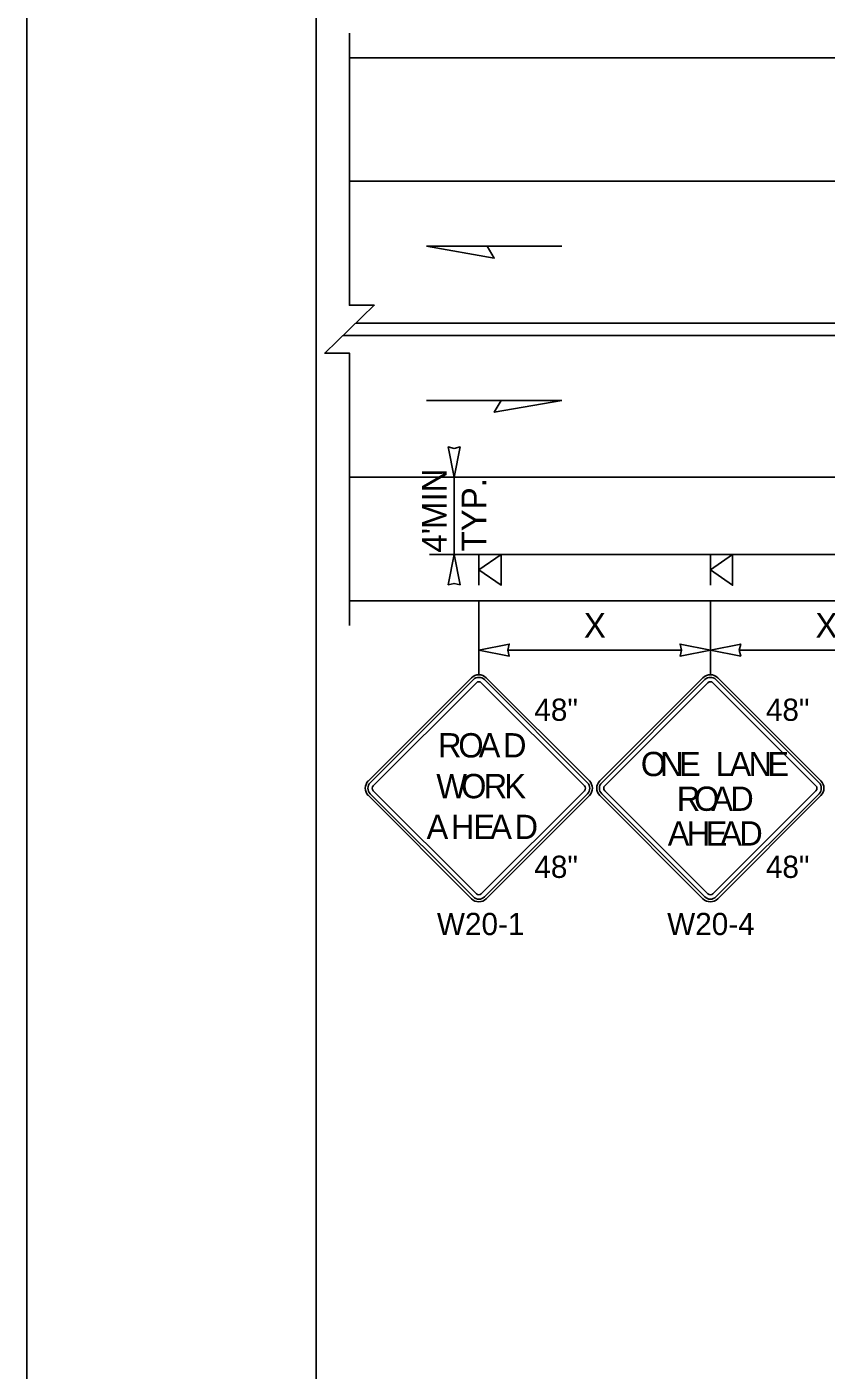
# Model space of a CAD drawing. Extents: x 99999.1 to 100095.7, y 99995 to 100010.7.
# Drawn here: x 99999.062 to 100001.652, y 100003.239 to 100007.592 of the extents above; entities that cross this region are included whole.
import ezdxf

# ---------------------------------------------------------------- set-up
doc = ezdxf.new("R2010")
doc.units = 0
for name, color, linetype in [('RD_ED_ShoulderPavedEdge', 7, 'Continuous'), ('RD_MK_LineDblYellowCenter', 7, 'Continuous'), ('RD_MK_LineEdgeWhite', 7, 'Continuous'), ('SH_GI_PlotLimits', 7, 'Continuous'), ('SH_GI_SheetBorder', 7, 'Continuous'), ('TR_SN_ConstructionSigns', 7, 'Continuous'), ('TR_WZ_PortableSignMountBlk-Org', 7, 'Continuous'), ('TR_WZ_WorkZoneDetails', 7, 'Continuous'), ('TR_WZ_WorkZoneTextCurrent', 7, 'Continuous')]:
    doc.layers.add(name, color=color, linetype=linetype)

msp = doc.modelspace()

# ---------------------------------------------------------------- linework, layer by layer
at = {"layer": 'RD_ED_ShoulderPavedEdge'}
for p, q in [((100000.1076, 100007.4923), (100015.6424, 100007.4923)), ((100000.1076, 100005.7323), (100015.6424, 100005.7323))]:
    msp.add_line(p, q, dxfattribs=at)
at = {"layer": 'RD_MK_LineDblYellowCenter'}
for p, q in [((100000.1282, 100006.6323), (100003.4767, 100006.6323)), ((100000.0869, 100006.5923), (100003.4767, 100006.5923))]:
    msp.add_line(p, q, dxfattribs=at)
at = {"layer": 'RD_MK_LineEdgeWhite'}
for p, q in [((100000.1076, 100007.0923), (100015.6424, 100007.0923)), ((100000.1076, 100006.1323), (100015.6424, 100006.1323))]:
    msp.add_line(p, q, dxfattribs=at)
at = {"layer": 'SH_GI_PlotLimits'}
msp.add_lwpolyline([(99999.0625, 99999.6875), (100016.0625, 99999.6875), (100016.0625, 100010.6875), (99999.0625, 100010.6875)], close=True, dxfattribs=at)
at = {"layer": 'SH_GI_SheetBorder'}
msp.add_line((100000, 100010.375), (100000, 100000), dxfattribs=at)
at = {"layer": 'TR_SN_ConstructionSigns'}
for p, q in [((100000.5028, 100005.4824), (100000.1687, 100005.1483)), ((100000.5088, 100005.4765), (100000.1746, 100005.1424)), ((100000.1846, 100005.1324), (100000.5187, 100005.4665)), ((100000.5346, 100005.4665), (100000.8687, 100005.1324)), ((100000.8787, 100005.1424), (100000.5445, 100005.4765)), ((100000.8846, 100005.1483), (100000.5505, 100005.4824)), ((100001.2528, 100005.4824), (100000.9187, 100005.1483)), ((100001.2588, 100005.4765), (100000.9246, 100005.1424)), ((100000.9346, 100005.1324), (100001.2687, 100005.4665)), ((100001.2846, 100005.4665), (100001.6187, 100005.1324)), ((100001.6287, 100005.1424), (100001.2945, 100005.4765)), ((100001.6346, 100005.1483), (100001.3005, 100005.4824)), ((100000.1746, 100005.1066), (100000.5088, 100004.7725)), ((100000.5187, 100004.7824), (100000.1846, 100005.1165)), ((100000.8687, 100005.1165), (100000.5346, 100004.7824)), ((100000.5445, 100004.7725), (100000.8787, 100005.1066)), ((100000.9246, 100005.1066), (100001.2588, 100004.7725)), ((100001.2687, 100004.7824), (100000.9346, 100005.1165)), ((100001.6187, 100005.1165), (100001.2846, 100004.7824)), ((100001.2945, 100004.7725), (100001.6287, 100005.1066)), ((100000.1687, 100005.1006), (100000.5028, 100004.7665)), ((100000.5505, 100004.7665), (100000.8846, 100005.1006)), ((100000.9187, 100005.1006), (100001.2528, 100004.7665)), ((100001.3005, 100004.7665), (100001.6346, 100005.1006))]:
    msp.add_line(p, q, dxfattribs=at)
for centre, radius, start, end in [((100000.5267, 100005.4586), 0.0338, 45, 135), ((100000.5267, 100005.4586), 0.0253, 45, 135), ((100000.5267, 100005.4586), 0.0113, 45, 135), ((100001.2767, 100005.4586), 0.0338, 45, 135), ((100001.2767, 100005.4586), 0.0253, 45, 135), ((100001.2767, 100005.4586), 0.0113, 45, 135), ((100000.1925, 100005.1245), 0.0338, 135, 225), ((100000.8608, 100005.1245), 0.0338, 315, 45), ((100000.9425, 100005.1245), 0.0338, 135, 225), ((100001.6108, 100005.1245), 0.0338, 315, 45), ((100000.1925, 100005.1245), 0.0253, 135, 225), ((100000.1925, 100005.1245), 0.0113, 135, 225), ((100000.8608, 100005.1245), 0.0113, 315, 45), ((100000.8608, 100005.1245), 0.0253, 315, 45), ((100000.9425, 100005.1245), 0.0253, 135, 225), ((100000.9425, 100005.1245), 0.0113, 135, 225), ((100001.6108, 100005.1245), 0.0113, 315, 45), ((100001.6108, 100005.1245), 0.0253, 315, 45), ((100000.5267, 100004.7904), 0.0338, 225, 315), ((100000.5267, 100004.7904), 0.0253, 225, 315), ((100000.5267, 100004.7904), 0.0113, 225, 315), ((100001.2767, 100004.7904), 0.0338, 225, 315), ((100001.2767, 100004.7904), 0.0253, 225, 315), ((100001.2767, 100004.7904), 0.0113, 225, 315)]:
    msp.add_arc(centre, radius, start, end, dxfattribs=at)
at = {"layer": 'TR_WZ_PortableSignMountBlk-Org'}
for p, q in [((100000.5267, 100005.7824), (100000.5267, 100005.8824)), ((100001.2767, 100005.7824), (100001.2767, 100005.8824))]:
    msp.add_line(p, q, dxfattribs=at)
for points in [[(100000.5267, 100005.8323), (100000.5985, 100005.8824), (100000.5985, 100005.7824)], [(100001.2767, 100005.8323), (100001.3485, 100005.8824), (100001.3485, 100005.7824)]]:
    msp.add_lwpolyline(points, close=True, dxfattribs=at)
at = {"layer": 'TR_WZ_WorkZoneDetails'}
for p, q in [((100000.5541, 100006.8816), (100000.7952, 100006.8816)), ((100000.5987, 100006.3816), (100000.3576, 100006.3816)), ((100000.3667, 100006.1323), (100000.5267, 100006.1323)), ((100000.4467, 100005.8824), (100000.4467, 100006.1323)), ((100000.3667, 100005.8824), (100000.5267, 100005.8824)), ((100000.5267, 100005.8824), (100003.5267, 100005.8824)), ((100000.5267, 100005.7326), (100000.5267, 100005.4923)), ((100001.2767, 100005.7323), (100001.2767, 100005.4923)), ((100001.1829, 100005.5723), (100000.6204, 100005.5723)), ((100001.9329, 100005.5723), (100001.3704, 100005.5723))]:
    msp.add_line(p, q, dxfattribs=at)
msp.add_lwpolyline([(100000.1076, 100005.6523), (100000.1076, 100006.5349), (100000.0275, 100006.5349), (100000.1876, 100006.6898), (100000.1076, 100006.6898), (100000.1076, 100007.5723)], dxfattribs=at)
for points in [[(100000.3576, 100006.8816), (100000.5764, 100006.843), (100000.5541, 100006.8816)], [(100000.7952, 100006.3816), (100000.5764, 100006.343), (100000.5987, 100006.3816)], [(100000.4467, 100006.1323), (100000.4274, 100006.2306), (100000.4467, 100006.2261), (100000.4659, 100006.2306)], [(100000.4467, 100005.8824), (100000.4274, 100005.7841), (100000.4467, 100005.7887), (100000.4659, 100005.7841)], [(100000.5267, 100005.5723), (100000.6249, 100005.5916), (100000.6204, 100005.5723), (100000.6249, 100005.5531)], [(100001.2767, 100005.5723), (100001.1784, 100005.5916), (100001.1829, 100005.5723), (100001.1784, 100005.5531)], [(100001.2767, 100005.5723), (100001.3749, 100005.5916), (100001.3704, 100005.5723), (100001.3749, 100005.5531)]]:
    msp.add_lwpolyline(points, close=True, dxfattribs=at)

# ---------------------------------------------------------------- texts
at = {"layer": 'TR_SN_ConstructionSigns'}
for s, p in [('48"', (100000.7064, 100005.343)), ('48"', (100001.4564, 100005.343)), ('48"', (100000.7064, 100004.8339)), ('48"', (100001.4564, 100004.8339)), ('W20-1', (100000.3908, 100004.6486)), ('W20-4', (100001.1367, 100004.6486))]:
    msp.add_text(s, height=0.072, rotation=360, dxfattribs=at).set_placement(p)
for s, height, p in [('R', 0.0788, (100000.3947, 100005.2243)), ('O', 0.0788, (100000.4601, 100005.2243)), ('A', 0.0788, (100000.5263, 100005.2243)), ('D', 0.0788, (100000.605, 100005.2243)), ('O', 0.0787, (100001.0514, 100005.1638)), ('N', 0.0787, (100001.1136, 100005.1638)), ('E', 0.0787, (100001.1751, 100005.1638)), ('L', 0.0787, (100001.294, 100005.1638)), ('A', 0.0787, (100001.3389, 100005.1638)), ('N', 0.0787, (100001.4003, 100005.1638)), ('E', 0.0787, (100001.4617, 100005.1638)), ('W', 0.0788, (100000.3888, 100005.0921)), ('O', 0.0788, (100000.4692, 100005.0921)), ('R', 0.0788, (100000.5424, 100005.0921)), ('K', 0.0788, (100000.6093, 100005.0921)), ('R', 0.0787, (100001.168, 100005.0513)), ('O', 0.0787, (100001.2239, 100005.0513)), ('A', 0.0787, (100001.2798, 100005.0513)), ('D', 0.0787, (100001.3412, 100005.0513)), ('A', 0.0788, (100000.3573, 100004.9599)), ('H', 0.0788, (100000.4361, 100004.9599)), ('E', 0.0788, (100000.5085, 100004.9599)), ('A', 0.0788, (100000.5637, 100004.9599)), ('D', 0.0788, (100000.6424, 100004.9599)), ('A', 0.0787, (100001.1388, 100004.9388)), ('H', 0.0787, (100001.2003, 100004.9388)), ('E', 0.0787, (100001.2617, 100004.9388)), ('A', 0.0787, (100001.3089, 100004.9388)), ('D', 0.0787, (100001.3704, 100004.9388))]:
    msp.add_text(s, height=height, dxfattribs=at).set_placement(p)
at = {"layer": 'TR_WZ_WorkZoneTextCurrent'}
for s, rotation, p in [('MIN', 90, (100000.4227, 100005.9648)), ('TYP.', 90, (100000.5507, 100005.892)), ("4'", 90, (100000.4227, 100005.8883)), ('X', 360, (100000.8669, 100005.6123)), ('X', 360, (100001.6169, 100005.6123))]:
    msp.add_text(s, height=0.08, rotation=rotation, dxfattribs=at).set_placement(p)

doc.saveas('drawing.dxf')
